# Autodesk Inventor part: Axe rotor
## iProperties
Author: Philippe
Shininess: 20.0
Angle Display Precision: 2
Document Length Units: 11269
Document Angle Units: 11283
Document Time Units: 11279
Document Mass Units: 11290
Document Length Units Precision: 3
Document Angle Units Precision: 2
Compacted: False
PropertySet Name: _Private Model Information
Created: 2002-08
Part Number: Axe rotor
Material: Acier doux
Document SubType Name: Modélisation
Designer: Philippe
Control State: 0
Master: False
Checked Out: False
PropertySet Name: Design Tracking Control
Density: 7.86
Volumn: 15.827940992608692
Area: 54.399289205210025
PropertySet Name: Model Information
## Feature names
1. Révolution1 [Revolution]
2. Extrusion1
3. Réseau circulaire1 [Circular Pattern]
4. Chanfrein1 [Chamfer]
